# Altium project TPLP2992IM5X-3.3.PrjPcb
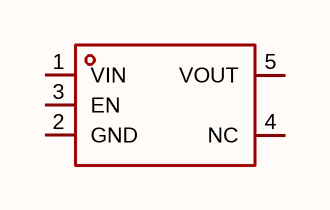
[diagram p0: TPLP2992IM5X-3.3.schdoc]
1 sheet, 1 parts. Net scope: global (net labels, ports and power ports of the same name join across sheets).

## Sheet TPLP2992IM5X-3.3.schdoc
size 127 x 101 mm

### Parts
U?  tplp2992im5x-3.3  [SOT-23-5_L2.9-W1.6-P0.95-LS2.8-BL]  (value not drawn)

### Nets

Not connected (* = marked no-connect by the designer): U? 1(VIN) 2(GND) 3(EN) 4(NC) 5(VOUT)

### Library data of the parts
U? = tplp2992im5x-3.3: 输出极性:正极;工作电压:24V;输出电压:3.3V;输出电流:300mA；500mA;电源纹波抑制比(PSRR):70dB@(1kHz);输出类型:固定;; Manufacturer: TECH PUBLIC(台舟); AddInBom: yes; ModelId: 018c57e721114987ae90467fe9f1d259; ModelTransform: 114.96,110.236,0,0,0,0,0,0,0; Output Configuration: 正极; Voltage - Supply: 24V; Output Voltage: 3.3V; Voltage Dropout: 420mV@(100mA); standby current: 4.5uA; Output Type: 固定; Number of Outputs: 1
